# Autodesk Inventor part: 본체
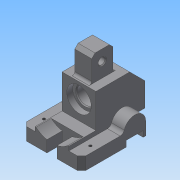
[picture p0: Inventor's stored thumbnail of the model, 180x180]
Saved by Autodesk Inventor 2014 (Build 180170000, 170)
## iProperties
Created: 2016-11
Part Number: 본체
Material: 일반
Document SubType Name: Modeling
Designer: net
Density: 1 g/cm^3
Appearance: 기본값
Author: net
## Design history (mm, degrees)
sketch "스케치1"
  geometry: L1 (-35, 38)-(35, 38); L2 (35, 38)-(35, -38); L3 (35, -38)-(-35, -38); L4 (-35, -38)-(-35, 38); 3 further points
  constraints: 8 end point, 2 midpoint, 2 parallel, 1 horizontal, 1 horizontal alignment, 1 perpendicular, 1 vertical alignment
  dimensions: "d0" = 70 distance of L2.end L3.end; "d1" = 76 distance of L3.end L1.start
extrude "돌출1" new body sketch "스케치1" distance "d2" = 15; taper "d3" = 0 deg
sketch "스케치2"
  geometry: L1 (0, 0)-(0, 76) reference; L2 (0, 76)-(15, 76) reference; L3 (0, 73)-(7, 73); L4 (7, 73)-(7, 53); L5 (7, 53)-(0, 53); L6 (0, 53)-(0, 73); 1 further point
  constraints: 8 end point, 2 parallel, 1 horizontal, 1 perpendicular, 1 point on line
  dimensions: "d4" = 3 distance between parallel lines of L3 L2; "d5" = 7 distance of L3.start L3.end; "d6" = 20 distance between parallel lines of L5 L3
extrude "돌출2" cut sketch "스케치2" stored distance "d7" = 15; taper "d8" = 0 deg
sketch "스케치5"
  geometry: L1 (-15, 73)-(-8, 73) reference; L2 (-8, 73)-(-8, 53) reference; L3 (-8, 53)-(-15, 53) reference; L4 (-15, 0)-(-15, 53) reference; L5 (-15, 0)-(0, 0) reference; L6 (0, 76)-(0, 0) reference; L7 (-15, 76)-(0, 76) reference; L8 (-15, 73)-(-15, 76) reference; A1 r 13 centre (0, 63) between (0, 50) and (0, 76); 1 further point
  constraints: 3 point on line, 2 point on circle, 1 centre point
  dimensions: "d15" = 13 distance from line of A1.centre L7; "d16" = 26 diameter of A1
extrude "돌출4" join sketch "스케치5" distance "d17" = 70; taper "d18" = 0 deg
sketch "스케치6"
  geometry: L1 (-35, -38)-(35, -38) reference; L2 (-20, -38)-(20, -38); L3 (20, -38)-(20, 52); L4 (20, 52)-(-20, 52); L5 (-20, 52)-(-20, -38); 2 further points
  constraints: 8 end point, 2 parallel, 1 horizontal, 1 midpoint, 1 perpendicular, 1 point on line, 1 vertical alignment
  dimensions: "d19" = 40 distance of L3.end L4.end; "d20" = 90 distance of L2.end L3.end
extrude "돌출5" join sketch "스케치6" distance "d21" = 5; taper "d22" = 0 deg
sketch "스케치7"
  geometry: L1 (20, -38)-(20, 13) reference; L2 (20, 37)-(-20, 37) reference; L3 (20, 37)-(20, 52) reference; L4 (20, 52)-(-20, 52) reference; L5 (-20, 52)-(-20, 37) reference; L6 (-20, 52)-(20, 52); L7 (20, 52)-(20, -6); L8 (20, -6)-(-20, -6); L9 (-20, -6)-(-20, 52); 1 further point
  constraints: 8 end point, 2 parallel, 1 horizontal, 1 perpendicular, 1 point on line
  dimensions: "d23" = 58 distance between parallel lines of L8 L6
extrude "돌출6" join sketch "스케치7" distance "d24" = 40; taper "d25" = 0 deg
sketch "스케치8"
  geometry: L1 (-20, 52)-(20, 52); L2 (20, 52)-(20, 38); L3 (20, 38)-(-20, 38); L4 (-20, 38)-(-20, 52); 1 further point
  constraints: 8 end point, 2 parallel, 1 horizontal, 1 perpendicular
extrude "돌출7" join sketch "스케치8" distance "d26" = 1; taper "d27" = 0 deg
sketch "스케치13"
  geometry: L1 (-20, -6)-(20, -6) reference; L2 (-10, -1)-(10, -1); L3 (10, -1)-(10, 24); L4 (10, 24)-(-10, 24); L5 (-10, 24)-(-10, -1); 2 further points
  constraints: 8 end point, 2 parallel, 1 horizontal, 1 midpoint, 1 perpendicular, 1 vertical alignment
  dimensions: "d38" = 20 distance of L2.start L2.end; "d39" = 5 distance between parallel lines of L2 L1; "d40" = 25 distance of L4.end L2.start
extrude "돌출10" join sketch "스케치13" distance "d41" = 30; taper "d42" = 0 deg
sketch "스케치15"
  geometry: L1 (45, 90)-(45, 32) reference; L2 (-1, 90)-(45, 90) reference; L3 (45, 90)-(45, 72); L4 (45, 72)-(27, 90); L5 (27, 90)-(45, 90); 1 further point
  constraints: 6 end point, 2 point on line, 1 collinear
  dimensions: "d43" = 18 distance of L1.start L3.end; "d44" = 45 deg angle of L3 L4
extrude "돌출11" cut sketch "스케치15" stored distance "d45" = 23; taper "d46" = 0 deg
sketch "스케치16"
  geometry: L1 (55, -20)-(-15, -20) reference; 3 further points
  constraints: 1 midpoint, 1 vertical alignment
  dimensions: "d47" = 42 distance from line of point (20, 22) L1
hole "구멍1" sketch "스케치16" at (20, 22) diameter "d48" = 20; stored, may be unused: countersink angle "d52" = 90 deg, drill point angle "d54" = 0 deg; dims "d49" = 6, "d50" = 29, "d51" = 7, "d53" = 8
sketch "스케치17"
  geometry: L1 (0, 25)-(30, 25) reference; L2 (-3.5, -5)-(-32.5, -5) reference; L3 (-32.5, 2)-(-3.5, 2) reference; L4 (-60, -37)-(-60, 16) reference; 2 further points
  dimensions: "d55" = 77 distance from line of L4 point (17, 12.5); "d56" = 12.5 distance from line of point (17, 12.5) L1
hole "구멍2" sketch "스케치17" at (17, 12.5) diameter "d57" = 8; stored, may be unused: countersink angle "d61" = 90 deg, drill point angle "d63" = 0 deg; dims "d58" = 6, "d59" = 29, "d60" = 7, "d62" = 8
chamfer "모따기1" distance "d64" = 4; stored, may be unused: second distance "d65" = 2, angle "d66" = 45 deg
sketch "스케치18"
  geometry: C1 r 10 at (35, 42) reference; C2 r 29 at (35, 42); 1 further point
  constraints: 1 centre point, 1 coincident
  dimensions: "d67" = 58 diameter of C2
extrude "돌출12" cut sketch "스케치18" distance "d68" = 18; taper "d69" = 0 deg
sketch "스케치19"
  geometry: L1 (70, 0)-(0, 0) reference; L2 (29, 0)-(41, 0); L3 (41, 0)-(41, 20); L4 (41, 20)-(29, 20); L5 (29, 20)-(29, 0); A1 r 29 centre (35, 42) between (16.106, 20) and (53.894, 20) reference; 2 further points
  constraints: 8 end point, 2 parallel, 1 horizontal, 1 midpoint, 1 perpendicular, 1 point on line, 1 vertical alignment
  dimensions: "d70" = 12 distance of L3.end L4.end; "d71" = 20 distance between parallel lines of L4 L1
extrude "돌출13" cut sketch "스케치19" distance "d72" = 18; taper "d73" = 0 deg
chamfer "모따기2" distance "d74" = 5; stored, may be unused: second distance "d75" = 2, angle "d76" = 45 deg
sketch "스케치20"
  geometry: L1 (-30, -38)-(-20, -38) reference; L2 (-35, 12)-(-35, -33) reference; L3 (27.5, -20)-(-27.5, -20); L4 (-18.894, -20)-(18.894, -20) reference; 3 further points
  constraints: 2 end point, 2 midpoint, 1 coincident, 1 perpendicular
  dimensions: "d77" = 55 distance of L3.start L3.end; "d78" = 18 distance from line of L1 L3.end
hole "구멍3" sketch "스케치20" at (27.5, -20), (-27.5, -20) diameter "d79" = 3.242; stored, may be unused: countersink angle "d83" = 90 deg, drill point angle "d85" = 0 deg; dims "d80" = 6, "d81" = 29, "d82" = 7, "d84" = 8
sketch "스케치21"
  geometry: L1 (5, 32)-(45, 32) reference; L2 (45, 72)-(45, 32) reference; 2 further points
  constraints: 1 other
  dimensions: "d86" = 25 distance from line of L1 point (27, 57); "d87" = 18 distance from line of point (27, 57) L2
feature "엠보싱1" sketch "스케치21" dims "d0" = 70, "d1" = 76, "d88" = 0.5, "d89" = 0
chamfer "모따기3" distance "d90" = 1; stored, may be unused: second distance "d91" = 2, angle "d92" = 45 deg
fillet "모깎기1" dims "d93" = 5
fillet "모깎기2" dims "d94" = 3
node "솔리드1"
node "투영된 루프1"
other parameters: "d12" = 26 (derived)
